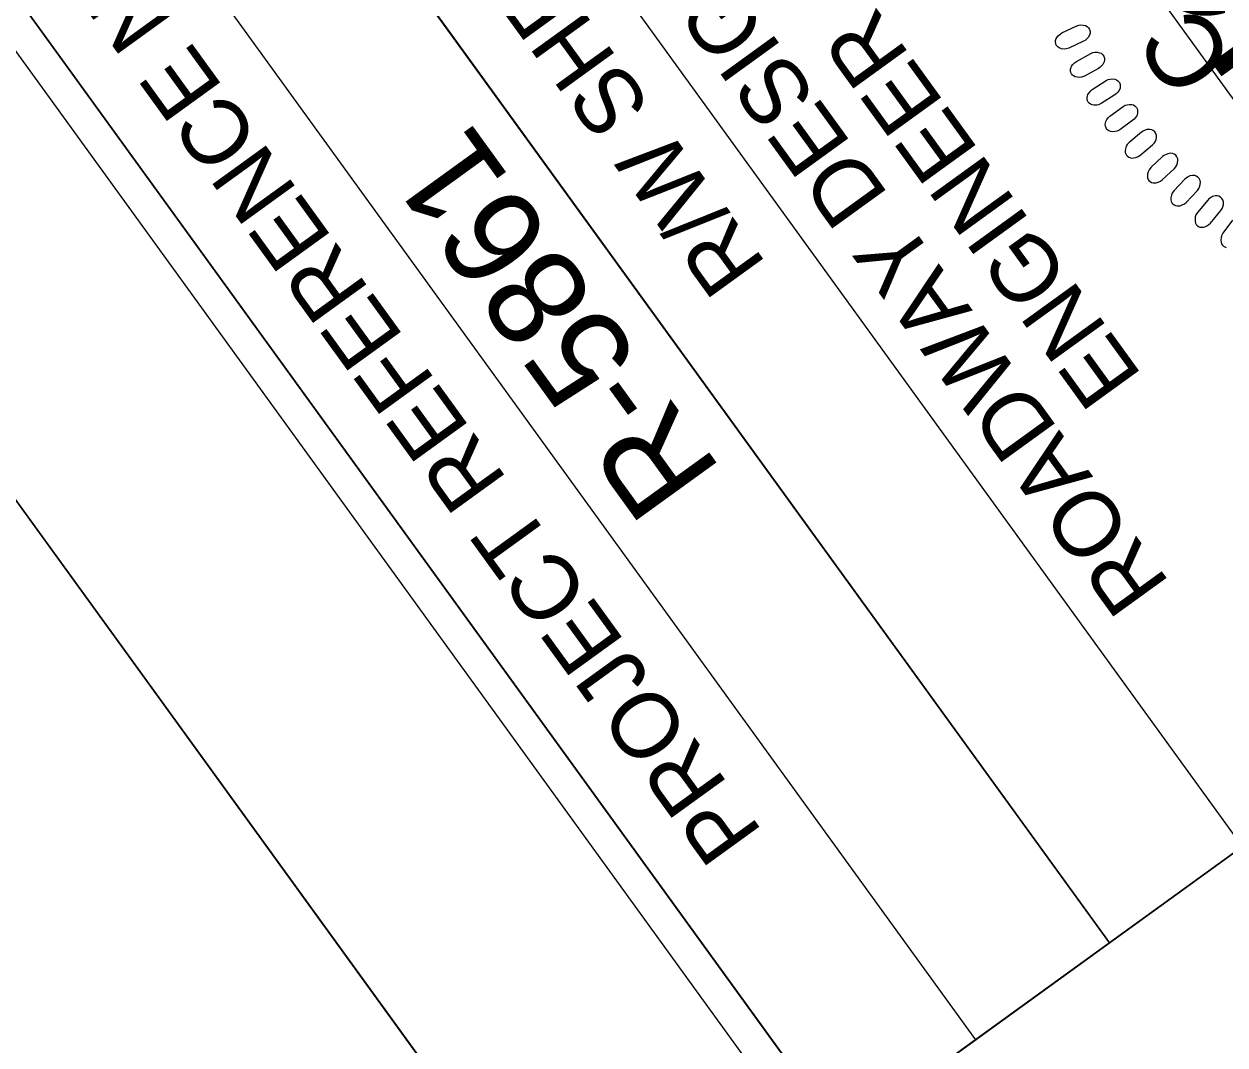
# Model space of a CAD drawing. Extents: x 474925 to 478950, y 494687 to 502905.
# Drawn here: x 475008.2 to 475099.5, y 502107.5 to 502185.1 of the extents above; entities that cross this region are included whole.
import ezdxf

# ---------------------------------------------------------------- set-up
doc = ezdxf.new("R2010")
doc.units = 0
for name, color, linetype in [('Prop Grid Mask', 7, 'Continuous'), ('Sheet Cutting Line CELL', 7, 'Continuous'), ('Sheet Data Field CELL', 7, 'Continuous'), ('Sheet PE Seal Cell', 7, 'Continuous'), ('Sheet Plan CELL', 7, 'Continuous'), ('Sheet Plan Layout CELL', 7, 'Continuous'), ('Sheet Plot Border Inside CELL', 7, 'Continuous'), ('Sheet Plot Border Outside CELL', 7, 'Continuous'), ('Sheet Sticker Incomplete CELL', 7, 'Continuous')]:
    doc.layers.add(name, color=color, linetype=linetype)

msp = doc.modelspace()

# ---------------------------------------------------------------- linework, layer by layer
at = {"layer": 'Prop Grid Mask'}
msp.add_lwpolyline([(475070.393, 502100.609), (475162.685, 501973.147), (475196.466, 501997.607), (475104.174, 502125.069)], close=True, dxfattribs=at)
at = {"layer": 'Sheet Cutting Line CELL'}
msp.add_line((474957.481, 502218.184), (475944.815, 500854.607), dxfattribs=at)
at = {"layer": 'Sheet PE Seal Cell'}
for points in [[(475088.734, 502183.821), (475087.624, 502183.302), (475087.409, 502183.242), (475087.261, 502183.231), (475087.059, 502183.261), (475086.919, 502183.302), (475086.799, 502183.369), (475086.719, 502183.447), (475086.652, 502183.54), (475086.623, 502183.65), (475086.6, 502183.771), (475086.61, 502183.892), (475086.656, 502184.029), (475086.702, 502184.116), (475086.809, 502184.241), (475086.946, 502184.371), (475087.082, 502184.46), (475088.217, 502184.999), (475088.38, 502185.05), (475088.525, 502185.069), (475088.708, 502185.055), (475088.882, 502185.013), (475088.995, 502184.959), (475089.116, 502184.842), (475089.197, 502184.715), (475089.224, 502184.563), (475089.224, 502184.447), (475089.187, 502184.29), (475089.084, 502184.109), (475088.951, 502183.972), (475088.845, 502183.89)], [(475089.874, 502181.759), (475088.798, 502181.17), (475088.588, 502181.097), (475088.441, 502181.076), (475088.238, 502181.093), (475088.094, 502181.126), (475087.971, 502181.186), (475087.886, 502181.258), (475087.815, 502181.347), (475087.778, 502181.456), (475087.747, 502181.574), (475087.749, 502181.695), (475087.787, 502181.835), (475087.828, 502181.925), (475087.927, 502182.057), (475088.056, 502182.195), (475088.185, 502182.291), (475089.284, 502182.901), (475089.443, 502182.963), (475089.587, 502182.99), (475089.77, 502182.988), (475089.946, 502182.957), (475090.063, 502182.91), (475090.191, 502182.801), (475090.28, 502182.68), (475090.317, 502182.529), (475090.324, 502182.414), (475090.297, 502182.254), (475090.206, 502182.068), (475090.08, 502181.923), (475089.981, 502181.834)], [(475091.118, 502179.743), (475090.081, 502179.087), (475089.876, 502179.001), (475089.73, 502178.971), (475089.526, 502178.976), (475089.382, 502178.999), (475089.254, 502179.051), (475089.165, 502179.119), (475089.088, 502179.203), (475089.045, 502179.308), (475089.006, 502179.425), (475089.001, 502179.546), (475089.029, 502179.687), (475089.065, 502179.78), (475089.155, 502179.918), (475089.275, 502180.064), (475089.398, 502180.168), (475090.457, 502180.845), (475090.612, 502180.917), (475090.754, 502180.954), (475090.937, 502180.963), (475091.114, 502180.943), (475091.234, 502180.904), (475091.369, 502180.803), (475091.466, 502180.687), (475091.512, 502180.539), (475091.525, 502180.424), (475091.508, 502180.263), (475091.429, 502180.072), (475091.314, 502179.919), (475091.219, 502179.824)], [(475092.48, 502177.816), (475091.487, 502177.097), (475091.287, 502176.999), (475091.142, 502176.959), (475090.94, 502176.951), (475090.794, 502176.965), (475090.663, 502177.009), (475090.57, 502177.071), (475090.488, 502177.15), (475090.439, 502177.252), (475090.392, 502177.367), (475090.38, 502177.486), (475090.399, 502177.63), (475090.429, 502177.725), (475090.511, 502177.867), (475090.621, 502178.021), (475090.737, 502178.133), (475091.75, 502178.875), (475091.901, 502178.957), (475092.041, 502179.002), (475092.222, 502179.023), (475092.402, 502179.014), (475092.523, 502178.982), (475092.663, 502178.89), (475092.767, 502178.78), (475092.822, 502178.636), (475092.843, 502178.522), (475092.838, 502178.361), (475092.77, 502178.164), (475092.664, 502178.005), (475092.576, 502177.904)], [(475093.142, 502176.918), (475092.195, 502176.138), (475092.049, 502175.97), (475091.975, 502175.841), (475091.915, 502175.646), (475091.892, 502175.501), (475091.902, 502175.364), (475091.938, 502175.258), (475091.994, 502175.159), (475092.081, 502175.085), (475092.18, 502175.012), (475092.292, 502174.969), (475092.436, 502174.952), (475092.535, 502174.957), (475092.694, 502174.999), (475092.871, 502175.067), (475093.007, 502175.151), (475093.982, 502175.945), (475094.099, 502176.07), (475094.178, 502176.193), (475094.244, 502176.364), (475094.28, 502176.54), (475094.281, 502176.665), (475094.227, 502176.825), (475094.147, 502176.953), (475094.021, 502177.043), (475093.916, 502177.092), (475093.758, 502177.126), (475093.551, 502177.111), (475093.37, 502177.048), (475093.251, 502176.989)], [(475094.736, 502175.062), (475093.84, 502174.224), (475093.705, 502174.047), (475093.639, 502173.913), (475093.592, 502173.716), (475093.578, 502173.57), (475093.596, 502173.434), (475093.639, 502173.329), (475093.701, 502173.234), (475093.792, 502173.166), (475093.895, 502173.099), (475094.01, 502173.063), (475094.155, 502173.055), (475094.254, 502173.066), (475094.409, 502173.119), (475094.581, 502173.198), (475094.713, 502173.29), (475095.636, 502174.144), (475095.744, 502174.276), (475095.816, 502174.404), (475095.871, 502174.578), (475095.896, 502174.756), (475095.888, 502174.881), (475095.825, 502175.037), (475095.737, 502175.16), (475095.606, 502175.241), (475095.498, 502175.284), (475095.338, 502175.308), (475095.133, 502175.28), (475094.956, 502175.206), (475094.841, 502175.14)], [(475096.43, 502173.349), (475095.589, 502172.457), (475095.466, 502172.272), (475095.408, 502172.134), (475095.373, 502171.934), (475095.369, 502171.788), (475095.395, 502171.652), (475095.444, 502171.552), (475095.512, 502171.46), (475095.607, 502171.398), (475095.715, 502171.338), (475095.832, 502171.309), (475095.977, 502171.31), (475096.075, 502171.327), (475096.227, 502171.39), (475096.393, 502171.479), (475096.519, 502171.58), (475097.386, 502172.489), (475097.486, 502172.628), (475097.55, 502172.76), (475097.594, 502172.938), (475097.608, 502173.117), (475097.592, 502173.241), (475097.519, 502173.392), (475097.423, 502173.509), (475097.287, 502173.583), (475097.177, 502173.618), (475097.016, 502173.633), (475096.813, 502173.592), (475096.641, 502173.507), (475096.53, 502173.433)], [(475098.165, 502171.759), (475097.381, 502170.816), (475097.27, 502170.623), (475097.22, 502170.482), (475097.199, 502170.28), (475097.203, 502170.133), (475097.239, 502170), (475097.293, 502169.902), (475097.367, 502169.816), (475097.466, 502169.759), (475097.577, 502169.706), (475097.696, 502169.685), (475097.84, 502169.695), (475097.937, 502169.718), (475098.085, 502169.79), (475098.245, 502169.89), (475098.364, 502169.998), (475099.173, 502170.96), (475099.264, 502171.105), (475099.319, 502171.241), (475099.352, 502171.421), (475099.355, 502171.6), (475099.33, 502171.723), (475099.248, 502171.871), (475099.146, 502171.981), (475099.006, 502172.046), (475098.893, 502172.075), (475098.732, 502172.079), (475098.532, 502172.025), (475098.365, 502171.93), (475098.259, 502171.849)]]:
    msp.add_lwpolyline(points, close=True, dxfattribs=at)
msp.add_lwpolyline([(475100.036, 502170.233), (475099.313, 502169.242), (475099.214, 502169.043), (475099.174, 502168.899), (475099.164, 502168.696), (475099.178, 502168.55), (475099.222, 502168.42), (475099.283, 502168.325), (475099.362, 502168.243), (475099.464, 502168.193), (475099.578, 502168.147)], dxfattribs=at)
at = {"layer": 'Sheet Plan CELL'}
for p, q in [((475090.699, 502115.3), (474973.361, 502277.308)), ((475090.699, 502115.3), (474973.361, 502277.308)), ((475080.552, 502107.936), (474963.237, 502269.977)), ((475090.699, 502115.3), (475100.814, 502122.623))]:
    msp.add_line(p, q, dxfattribs=at)
for points in [[(474953.05, 502262.647), (475832.788, 501047.669), (476683.252, 501663.47), (475803.528, 502878.428)], [(476683.281, 501663.491), (475832.823, 501047.663), (475070.379, 502100.597), (475191.917, 502188.605), (475074.61, 502350.635), (475803.528, 502878.428)], [(475070.379, 502100.586), (474953.05, 502262.647), (474973.361, 502277.308), (475090.699, 502115.3)], [(475100.814, 502122.623), (475042.137, 502203.66), (475133.268, 502269.646), (475191.917, 502188.605)]]:
    msp.add_lwpolyline(points, close=True, dxfattribs=at)
at = {"layer": 'Sheet Plan Layout CELL'}
msp.add_lwpolyline([(475297.285, 502147.842), (475156.955, 502341.646), (474985.643, 502217.634), (475125.987, 502023.809)], close=True, dxfattribs=at)
at = {"layer": 'Sheet Plot Border Inside CELL'}
msp.add_lwpolyline([(476807.904, 501495.6), (475830.83, 502844.985), (474976.319, 502226.269), (475953.391, 500876.866)], close=True, dxfattribs=at)
at = {"layer": 'Sheet Plot Border Outside CELL'}
msp.add_lwpolyline([(475811.793, 502905.401), (476799.127, 501541.824), (475912.215, 500899.631), (474924.88, 502263.208)], close=True, dxfattribs=at)
at = {"layer": 'Sheet Sticker Incomplete CELL'}
msp.add_lwpolyline([(475130.803, 502177.117), (475111.769, 502163.335), (475025.557, 502282.4), (475044.591, 502296.182)], close=True, dxfattribs=at)

# ---------------------------------------------------------------- texts
at = {"layer": 'Sheet Data Field CELL'}
msp.add_text('R-5861', height=7.5, rotation=125.90742, dxfattribs=at).set_placement((475061.33, 502151.151))
at = {"layer": 'Sheet PE Seal Cell'}
msp.add_text('C', height=5.669, rotation=123.4951, dxfattribs=at).set_placement((475100.376, 502182.267))
at = {"layer": 'Sheet Plan CELL'}
for s, p in [('R/W SHEET NO.', (475064.712, 502166.856)), ('PROJECT REFERENCE NO.', (475064.426, 502123.685)), ('ROADWAY DESIGN', (475095.363, 502142.598)), ('ENGINEER', (475093.265, 502158.347))]:
    msp.add_text(s, height=5.0001, rotation=125.90742, dxfattribs=at).set_placement(p)
at = {"layer": 'Sheet Sticker Incomplete CELL'}
for s, height, p in [('INCOMPLETE PLANS', 11.52, (475116.078, 502177.504)), ('DO NOT USE FOR R/W ACQUISITION', 5.76, (475119.801, 502184.213))]:
    msp.add_text(s, height=height, rotation=125.90742, dxfattribs=at).set_placement(p)

doc.saveas('drawing.dxf')
